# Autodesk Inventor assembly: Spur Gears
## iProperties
Created: 2008-01
Part Number: Spur Gears
Document SubType Name: Assembly
Designer: eruiz-tagle
Mass: 0.924245 g
Surface Area: 2.83839 cm^2
Volume: 0.117738 cm^3
Density: 7.85 g/cm^3
ClientObjectVersion: 1
Author: eruiz-tagle
